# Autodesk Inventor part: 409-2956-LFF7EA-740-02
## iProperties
Created: 2010-06
Part Number: 409-2956-LFF7EA-740-02
Material: Sch40 CS PIPE SEAMLESS
Description: PIPE
Document SubType Name: Modeling
Designer: S. Boerckel
Engineer: Steve Boerckel
Mass: 9098.81 g
Surface Area: 4254.05 cm^2
Volume: 1159.08 cm^3
Density: 7.85 g/cm^3
Cost Center: 4"
SMR: =<COST CENTER> - <Material>
Length: 31.740 in
Title: 4"
Author: S. Boerckel
Revision Number: B
Subject: DEMIN WATER FORWARDING PUMP SKID-7EA
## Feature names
1. Extrusion1
